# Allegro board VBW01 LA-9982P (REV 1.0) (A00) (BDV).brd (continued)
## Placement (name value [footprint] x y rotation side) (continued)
PC817  -  [C_0402NEW]  201.58 51.05 90 bottom
PC818  -  [C_0402NEW]  206.04 53.73 180 bottom
PC819  -  [C_0402NEW]  199.11 59.26 180 bottom
PC820  -  [C_0402NEW]  199.11 58.37 180 bottom
PC821  -  [C_0402NEW]  201.59 54.62 180 top
PC831  -  [C_0402NEW]  213.38 74.05 0 top
PC832  -  [C_0402NEW]  213.38 73.16 0 top
PC835  -  [C_0603NEW]  194.53 89.16 90 top
PC836  -  [C_D1]  204.04 84.58 0 top
PC837  -  [C_D1]  200.82 86.26 270 bottom
PC838  -  [C_D1]  195.99 84.68 270 bottom
PC839  -  [C_D1]  191.23 84.68 270 bottom
PC840  -  [C_0402NEW]  181.44 122.2 0 top
PC841  -  [C_0402NEW]  181.5 117.69 0 top
PC842  -  [C_0402NEW]  182.08 118.93 90 top
PC843  -  [C_0402NEW]  179.54 117.69 0 top
PC844  -  [C_0402NEW]  177.34 117.24 180 top
PC845  -  [C_0402NEW]  177.34 118.7 180 top
PC846  -  [C_0402NEW]  176.49 120.67 0 top
PC847  -  [C_0402NEW]  179.59 115.96 0 top
PC848  -  [C_0402NEW]  181.37 115.96 0 top
PC849  -  [C_0402NEW]  173.88 102.2 270 bottom
PC850  -  [C_0402NEW]  178.21 119.85 270 top
PC851  -  [C_0402NEW]  179.09 119.45 0 top
PC852  -  [C_0402NEW]  178.73 115.71 180 top
PC853  -  [C_0402NEW]  175.43 120.67 180 top
PC854  -  [C_0402NEW]  174.46 117.24 0 top
PC855  -  [C_0402NEW]  175.43 122.13 180 top
PC856  -  [C_0402NEW]  179.28 122.2 0 top
PC857  -  [C_0402NEW]  179.34 123.66 0 top
PC858  -  [C_0402NEW]  181.44 123.66 0 top
PC859  -  [C_0402NEW]  179.28 120.74 0 top
PC860  -  [C_0402NEW]  181.44 120.74 0 top
PC861  -  [C_0402NEW]  176.95 115.71 180 top
PC862  -  [C_0402NEW]  178.2 112.47 0 top
PC863  -  [C_0402NEW]  175.17 115.71 180 top
PC864  -  [C_0402NEW]  176.36 122.13 0 top
PC865  -  [C_0402NEW]  176.49 123.63 0 top
PC866  -  [C_0402NEW]  174.46 118.7 0 top
PC867  -  [C_0603NEW]  192.81 89.16 90 top
PC868  -  [C_0603NEW]  196.31 89.16 90 top
PC869  -  [C_0402NEW]  207.62 56.21 180 top
PC870  -  [C_0603NEW]  198.02 89.16 90 top
PC871  -  [C_0402NEW]  173.58 117.55 90 top
PC872  -  [C_0402NEW]  172.18 117.02 90 top
PC873  -  [C_0402NEW]  172.18 119.73 270 top
PC901  -  [C_0805NEW]  97.44 122.73 90 top
PC902  -  [C_0805NEW]  100.3 122.67 90 top
PC903  -  [C_0805NEW]  102.77 122.67 90 top
PC904  -  [C_0805NEW]  105.31 122.67 90 top
PC905  -  [C_0805NEW]  107.79 122.67 90 top
PC906  -  [C_0805NEW]  110.33 122.67 90 top
PC907  -  [C_0805NEW]  112.8 122.67 90 top
PC908  -  [C_0805NEW]  96.93 117.9 90 top
PC909  -  [C_0805NEW]  100.65 137.55 0 top
PC910  -  [C_0805NEW]  96.87 114.79 90 top
PC911  -  [C_0805NEW]  97.35 135.33 0 top
PC912  -  [C_0805NEW]  110.81 135.33 0 top
PC913  -  [C_0805NEW]  110.75 137.49 0 top
PC914  -  [C_0805NEW]  107.45 135.33 0 top
PC915  -  [C_0805NEW]  107.38 137.49 0 top
PC916  -  [C_0805NEW]  104.08 135.33 0 top
PC917  -  [C_0805NEW]  100.71 135.33 0 top
PC918  -  [C_0805NEW]  110.81 133.93 0 bottom
PC919  -  [C_0805NEW]  107.45 133.93 0 bottom
PC920  -  [C_0805NEW]  104.08 133.93 0 bottom
PC921  -  [C_0805NEW]  100.71 133.93 0 bottom
PC922  -  [C_0805NEW]  103.95 137.55 0 top
PC923  -  [C_0805NEW]  97.35 133.93 0 bottom
PC1100  -  [C_0402NEW]  178.64 173.37 0 top
PC1101  -  [C_0402NEW]  178.64 174.25 0 top
PC1102  -  [C_0805NEW]  178.82 175.59 0 top
PC1103  -  [C_0603NEW]  183.16 170.25 90 top
PC1104  -  [C_0402NEW]  188.19 172.03 180 bottom
PC1105  -  [C_0603NEW]  183.67 173.05 90 top
PC1106  -  [C_0402NEW]  181.45 170.11 90 top
PC1108  -  [C_MP6VU330MC6]  182.65 167.14 0 bottom
PC1200  -  [C_0402NEW]  183.99 186.18 90 bottom
PC1201  -  [C_0805NEW]  190.85 185.34 90 bottom
PC1202  -  [C_0805NEW]  177.8 177.49 0 bottom
PC1203  -  [C_0402NEW]  175.88 182.71 180 bottom
PC1204  -  [C_0805NEW]  177.8 179.21 0 bottom
PC1205  -  [C_0603NEW]  176.37 183.78 180 bottom
PC1206  -  [C_0805NEW]  189.07 185.34 90 bottom
PC1207  -  [C_0805NEW]  189.07 177.01 270 bottom
PC1209  -  [C_0402NEW]  175.88 181.82 180 bottom
PC1210  -  [C_0603NEW]  175.81 186.52 270 bottom
PC1211  -  [C_0805NEW]  190.78 177.01 270 bottom
PC1212  -  [C_0603NEW]  181.13 176.16 90 bottom
PC1213  -  [C_0603NEW]  178.22 185.12 90 bottom
PC1214  -  [C_0402NEW]  173.46 184.16 180 bottom
PC1300  -  [C_0805NEW]  199.1 73.38 270 top
PC1301  -  [C_0805NEW]  195 60.72 180 bottom
PC1302  -  [C_0402NEW]  194.67 62.62 180 top
PC1303  -  [C_0805NEW]  193.64 73.38 270 top
PC1304  -  [C_0402NEW]  197.15 65.03 180 top
PC1305  -  [C_0805NEW]  197.32 73.38 270 top
PC1306  -  [C_0402NEW]  197.77 63.52 270 top
PC1307  -  [C_0402NEW]  196.94 65.11 270 bottom
PC1308  -  [C_0805NEW]  195.55 73.38 270 top
PD1  -  [IP4223CZ6_SO6]  142.24 185.05 270 bottom
PD101  -  [L03ESDL5V0CG3-2_SOT-523-3]  122.63 13.98 90 top
PD701  -  [RB751V-40_SOD323-2]  162.53 171.02 0 top
PH1  -  [R_0402NEW]  106.19 113.74 0 top
PH501  -  [R_0402NEW]  95.58 143.46 0 bottom
PH502  -  [R_0402NEW]  111.93 144.16 180 bottom
PH800  -  [R_0402NEW]  203.86 79.08 270 bottom
PJP100  -  [JUMP_43X118]  134.78 13.39 270 bottom
PJP101  -  [JUMP_43X118]  122.58 13.51 270 bottom
PJP102  -  [JUMP_43X118]  140.05 13.39 270 bottom
PJP103  -  [JUMP_43X118]  117.31 13.51 270 bottom
PJP200  -  [JUMP_43X118]  149.32 27.85 90 top
PJP201  -  [JUMP_43X118]  144.81 27.59 90 bottom
PJP203  -  [JUMP_43X39]  155.03 29.36 270 bottom
PJP300  -  [JUMP_43X118]  143.67 140.45 270 top
PJP400  -  [JUMP_43X79]  108.3 20.35 90 bottom
PJP401  -  [JUMP_43X79]  112.11 31.27 90 bottom
PJP600  -  [JUMP_43X79]  213.98 90.82 0 bottom
PJP601  -  [JUMP_43X79]  215.29 96.76 270 top
PJP1100  -  [JUMP_43X118]  182.78 162.32 270 bottom
PJP1101  -  [JUMP_43X118]  188.12 162.32 270 bottom
PJP1200  -  [JUMP_43X118]  192.27 181.37 0 bottom
PJP1300  -  [JUMP_43X79]  195.74 76.19 270 top
PJP1301  -  [JUMP_43X79]  194.66 58.76 270 bottom
PJPDC  -  [ACES_50299-00501-003_5P]  136.9 178.4 270 bottom
PL1  -  [CHT_C8BBPH853025_2P]  140.43 174 270 bottom
PL2  -  [CHT_C8BBPH853025_2P]  132.93 182.51 180 bottom
PL3  -  [CHENG_SMB3025500YA_2P]  155.86 180.26 90 bottom
PL4  -  [CHT_C8BBPH853025_2P]  132.87 166.13 180 bottom
PL100  -  [VISHAY_IHLP-2525CZ-01_2P]  135.35 25.41 0 bottom
PL101  -  [VISHAY_IHLP-2525CZ-01_2P]  120.17 25.57 180 bottom
PL102  -  [CYNTE_PCMB053T-1R0MS_2P]  127.73 31.78 270 bottom
PL200  -  [TAI-T_VMPI0703AR-1R0M-Z01_2P]  145.4 15.12 0 bottom
PL201  -  [L_1812-1806]  165.32 20.69 270 bottom
PL301  -  [CYNTE_PCMB063T-1R0MS_2P]  144.08 150.59 270 bottom
PL302  -  [L_1812-1806]  134.42 158.32 0 bottom
PL400  -  [CYNTE_PH041H-1R0MS_2P]  107.58 28.97 90 bottom
PL501  -  [L_1812-1806]  135.09 146.53 90 bottom
PL502  -  [TOKO_FDUE1040J-H-R36M-P3_4P]  109.67 140.16 180 bottom
PL600  -  [CYNTE_PH041H-1R0MS_2P]  219.55 94.6 90 bottom
PL701  -  [TOKO_FDVE1040-H-2R2M-P3_2P]  155.38 172.6 180 bottom
PL702  -  [CYNTE_PCMB053T-1R0MS_2P]  146.89 163.46 0 bottom
PL800  -  [L_1812-1806]  217.55 77.93 180 top
PL802  -  [MAG_MMD-12CE-R36M-M1L_2P]  211.17 74.49 90 bottom
PL1100  -  [TAI-T_HCB2012KF-121T50_2P]  175.16 177.38 90 top
PL1101  -  [PANAS_ETQP3W2R2WFN_2P]  177.13 170.14 90 bottom
PL1200  -  [CYNTE_PCMB063T-1R0MS_2P]  183.29 181.24 0 bottom
PL1201  -  [L_1812-1806]  171.44 178.76 0 bottom
PL1300  -  [VISHAY_IHLP-2525CZ-01_2P]  195.55 71.38 90 bottom
PQ1  -  [2N7002DW-T-R7_SOT363-6]  128.22 173.52 0 top
PQ2  -  [2N7002DW-T-R7_SOT363-6]  128.9 168.81 270 top
PQ3  -  [2N7002DW-T-R7_SOT363-6]  128.96 163.6 270 top
PQ4  -  [SSM3K7002FU_SC70-3]  128.17 179.34 0 top
PQ5  -  [RHU002N06_SOT323-3]  133.89 187.37 0 bottom
PQ6  -  [FDV301N_NL_SOT23-3]  128.97 186.57 90 bottom
PQ101  -  [SIS412DN-T1-GE3_POWERPAK8-5]  133.1 26.55 90 top
PQ102  -  [SIS412DN-T1-GE3_POWERPAK8-5]  130.23 24.72 270 top
PQ103  -  [SIS412DN-T1-GE3_POWERPAK8-5]  121.78 28.7 270 top
PQ104  -  [SIS412DN-T1-GE3_POWERPAK8-5]  124.65 22.93 90 top
PQ200  -  [SIS412DN-T1-GE3_POWERPAK8-5]  154.68 16.29 90 bottom
PQ201  -  [SIS412DN-T1-GE3_POWERPAK8-5]  157.04 14.46 270 bottom
PQ701  -  [CSD87312Q3E_SON8-4]  140.24 167.98 0 bottom
PQ702  -  [AO4407AL_SO8]  147.12 178.89 90 bottom
PQ703  -  [MDU1516URH_POWERDFN56-8-5]  156.11 169.3 180 top
PQ704  -  [MDU1516URH_POWERDFN56-8-5]  149.77 169.32 180 top
PQ705  -  [MDU1511RH_POWERDFN56-8-5]  159.54 171.17 90 top
PQ706  -  [SSM3K7002FU_SC70-3]  135.79 168.22 180 top
PQ708  -  [SSM3K7002FU_SC70-3]  171.48 173.11 0 top
PQ800  -  [SIR472DP-T1-GE3_POWERPAK8-5]  205.77 69.39 270 top
PQ801  -  [SIR818DP-T1_POWERPAK-SO8-5]  214.09 65.47 270 bottom
PQ802  -  [SIR818DP-T1_POWERPAK-SO8-5]  214.09 71.26 270 bottom
PQ803  -  [SIR472DP-T1-GE3_POWERPAK8-5]  205.77 75.39 270 top
PQ1100  -  [SIS412DN-T1-GE3_POWERPAK8-5]  175.38 172.25 0 top
PQ1101  -  [SIS412DN-T1-GE3_POWERPAK8-5]  180.28 174.79 270 bottom
PQ1201  -  [2N7002W-T-R7_SOT323-3]  173.45 186.99 0 bottom
PR1  -  [R_0402NEW]  128.63 171.02 0 top
PR3  -  [R_0402NEW]  132.35 185.62 0 top
PR4  -  [R_0402NEW]  130.57 185.62 0 top
PR5  -  [R_1206NEW]  131.27 175.59 270 top
PR6  -  [R_0402NEW]  132.5 182.7 180 top
PR7  -  [R_0402NEW]  128.86 177.49 0 top
PR8  -  [R_0402NEW]  134.22 187.46 180 top
PR9  -  [R_0402NEW]  134.28 182.7 180 top
PR10  -  [R_0402NEW]  129.77 176.6 180 top
PR15  -  [R_0402NEW]  138.54 184.92 180 bottom
PR16  -  [R_0402NEW]  136.76 184.92 180 bottom
PR18  -  [R_0402NEW]  141.88 183.65 0 top
PR20  -  [R_0402NEW]  141.88 184.54 0 top
PR23  -  [R_0402NEW]  129.94 179.91 0 top
PR24  -  [R_0402NEW]  181.96 45.02 90 bottom
PR26  -  [R_0402NEW]  130.85 181.68 180 top
PR27  -  [R_0402NEW]  129.11 178.89 0 top
PR28  -  [R_0402NEW]  128.38 166.38 180 top
PR29  -  [R_0402NEW]  127.65 170 0 top
PR30  -  [R_0402NEW]  127.54 161.8 90 top
PR31  -  [R_0402NEW]  131.98 167.7 90 top
PR32  -  [R_0402NEW]  132.11 162.71 270 top
PR33  -  [R_0402NEW]  130.51 166.32 0 top
PR100  -  [R0402_0OHM-NEW]  120.98 13.13 180 top
PR101  -  [R0402_0OHM-NEW]  120.98 14.91 180 top
PR102  -  [R_0402NEW]  120.98 14.02 180 top
PR103  -  [R_0402NEW]  132.44 16.68 180 top
PR104  -  [R_0402NEW]  126.71 12.98 270 top
PR105  -  [R_0402NEW]  125.82 12.98 270 top
PR106  -  [R_0402NEW]  125.72 12.99 270 bottom
PR107  -  [R_0402NEW]  130.71 12.06 90 top
PR108  -  [R_0402NEW]  131.6 12.98 270 top
PR109  -  [R_0402NEW]  128.93 12.06 90 top
PR111  -  [R_0402NEW]  124.12 17.28 180 top
PR112  -  [R_1206NEW]  119.98 25.06 270 top
PR113  -  [R_1206NEW]  134.97 24.87 270 top
PR114  -  [R_0402NEW]  124.12 15.5 180 top
PR200  -  [R_0603NEW]  154.85 22.95 90 bottom
PR201  -  [R_0402NEW]  162.92 25.22 180 bottom
PR202  -  [R_0402NEW]  162.92 27 180 bottom
PR203  -  [R_1206NEW]  161.32 10.74 0 bottom
PR204  -  [R_0402NEW]  161.47 29.11 180 bottom
PR205  -  [R_0402NEW]  158.59 20.28 90 bottom
PR206  -  [R_0603NEW]  162.09 21.42 270 bottom
PR207  -  [R_0402NEW]  161.47 28.22 180 bottom
PR208  -  [R_0402NEW]  162.92 23.44 180 bottom
PR300  -  [R_0402NEW]  148.17 148.34 0 bottom
PR301  -  [R_0402NEW]  148.17 149.23 0 bottom
PR302  -  [R_1206NEW]  139.54 146.56 90 bottom
PR303  -  [R_0603NEW]  147.04 156.85 0 bottom
PR304  -  [R_0402NEW]  149.08 152.78 180 bottom
PR305  -  [R_0402NEW]  148.62 153.72 90 bottom
PR306  -  [R_0402NEW]  148.17 151.89 0 bottom
PR307  -  [R_0402NEW]  149.39 155.5 90 bottom
PR308  -  [R_0402NEW]  149.08 151.01 180 bottom
PR401  -  [R_0402NEW]  113.68 26.85 270 bottom
PR402  -  [R_0402NEW]  111.9 23.78 90 bottom
PR403  -  [R_0402NEW]  112.79 24.69 270 bottom
PR404  -  [R_0402NEW]  112.79 26.85 270 bottom
PR405  -  [R_0603NEW]  108.34 26.97 180 bottom
PR501  -  [R_0402NEW]  88.61 141.22 90 bottom
PR502  -  [R_0402NEW]  85.94 141.22 90 bottom
PR503  -  [R_0402NEW]  88.48 138.94 90 top
PR504  -  [R_0402NEW]  86.83 141.22 90 bottom
PR505  -  [R_0402NEW]  86.71 138.94 90 top
PR506  -  [R_0402NEW]  85.82 138.94 90 top
PR507  -  [R_0402NEW]  87.72 141.22 90 bottom
PR508  -  [R_0402NEW]  91.66 142.19 270 bottom
PR509  -  [R_0402NEW]  87.6 138.94 90 top
PR510  -  [R_0402NEW]  87.01 137.23 0 top
PR512  -  [R_0402NEW]  89.37 138.94 90 top
PR513  -  [R_0402NEW]  91.15 138.94 90 top
PR514  -  [R_0402NEW]  90.77 141.29 90 bottom
PR515  -  [R_0402NEW]  92.98 141.74 0 bottom
PR516  -  [R_0603NEW]  83.98 135.77 0 bottom
PR517  -  [R_0402NEW]  92.98 140.85 0 bottom
PR518  -  [R_0402NEW]  92.93 143.06 90 bottom
PR519  -  [R_0603NEW]  88.87 131.89 90 bottom
PR522  -  [R_0402NEW]  85.46 139.01 180 bottom
PR524  -  [R_0402NEW]  84.55 137.23 0 bottom
PR526  -  [R_0402NEW]  87.79 132.59 90 bottom
PR528  -  [R_0402NEW]  86.9 132.59 90 bottom
PR529  -  [R_0402NEW]  92.66 132.6 0 bottom
PR530  -  [R_0402NEW]  84.53 134.69 0 bottom
PR531  -  [R_0402NEW]  90.9 132.66 90 bottom
PR532  -  [R_0402NEW]  93.58 133.49 180 bottom
PR533  -  [R_0402NEW]  85.45 134.69 180 top
PR534  -  [R_1206NEW]  108.42 143.2 0 top
PR535  -  [R0402_0OHM-NEW]  85.46 138.12 180 bottom
PR536  -  [R_0603NEW]  116.36 139.9 0 bottom
PR540  -  [R_0402NEW]  84.53 135.58 0 top
PR601  -  [R_0402NEW]  218.29 93.36 180 top
PR602  -  [R_0402NEW]  221.26 89.79 90 bottom
PR603  -  [R_0402NEW]  222.16 88.91 180 bottom
PR604  -  [R_0402NEW]  219.17 93.37 270 top
PR605  -  [R_0603NEW]  216.06 95.13 270 bottom
PR701  -  [R_0402NEW]  142.9 163.89 90 bottom
PR702  -  [R_1206_4P-D]  139.7 162.19 0 bottom
PR703  -  [R_0402NEW]  143.79 164.81 270 bottom
PR704  -  [R_0402NEW]  166.78 165.95 270 bottom
PR705  -  [R_1206NEW]  164.49 163.08 90 top
PR706  -  [R_0402NEW]  147.36 183.91 180 bottom
PR707  -  [R_0402NEW]  169.07 164.97 90 top
PR708  -  [R_0402NEW]  167.67 173.04 90 top
PR709  -  [R_0603NEW]  163.92 169.56 180 top
PR710  -  [R_0402NEW]  168.56 173.04 90 top
PR711  -  [R_0402NEW]  172.25 167.21 180 top
PR712  -  [R_0402NEW]  170.02 165.89 270 top
PR713  -  [R_0402NEW]  171.34 171.65 0 top
PR714  -  [R0402_0OHM-NEW]  172.25 170.76 180 top
PR715  -  [R0402_0OHM-NEW]  172.25 169.87 180 top
PR716  -  [R_1206_4P-D]  143.73 176.64 90 bottom
PR717  -  [R_0402NEW]  167.67 165.95 270 bottom
PR720  -  [R_1206NEW]  138.2 169.94 180 top
PR721  -  [R_0402NEW]  143.81 165.68 180 bottom
PR722  -  [R_1206NEW]  156.37 177.01 0 top
PR723  -  [R_0402NEW]  171.34 166.32 0 top
PR724  -  [R_0402NEW]  171.07 176.22 0 top
PR802  -  [R_0603NEW]  201.39 60.08 90 bottom
PR803  -  [R_0402NEW]  209.91 56.02 180 bottom
PR804  -  [R_0402NEW]  206.71 57.1 0 top
PR805  -  [R_1206NEW]  211.17 62.69 0 top
PR806  -  [R_0402NEW]  209.91 56.91 180 bottom
PR807  -  [R_0402NEW]  209.91 58.68 180 bottom
PR808  -  [R_0402NEW]  209.91 54.24 180 bottom
PR809  -  [R_0402NEW]  209.91 57.8 180 bottom
PR810  -  [R_0402NEW]  208.7 59 180 top
PR811  -  [R_0402NEW]  206.96 60.46 0 top
PR812  -  [R_0402NEW]  209.91 59.57 180 bottom
PR813  -  [R_0402NEW]  203.37 51.95 180 bottom
PR814  -  [R_0603NEW]  205.9 61.73 90 bottom
PR815  -  [R_0402NEW]  206.72 54.35 90 top
PR816  -  [R_0402NEW]  199.11 56.59 180 bottom
PR817  -  [R_0402NEW]  206.04 52.84 180 bottom
PR818  -  [R_0402NEW]  203.37 51.06 180 bottom
PR819  -  [R_0402NEW]  207.79 58.11 0 top
PR820  -  [R_0402NEW]  205.32 53.49 270 top
PR821  -  [R_0402NEW]  204.24 53.74 270 bottom
PR822  -  [R_0603NEW]  201.51 58.68 180 bottom
PR823  -  [R_0603NEW]  201.51 58.68 180 top
PR824  -  [R_0402NEW]  201.58 60.67 270 top
PR825  -  [R_0402NEW]  201.59 55.51 180 bottom
PR826  -  [R_0402NEW]  213.91 59.51 180 bottom
PR827  -  [R_0402NEW]  199.11 57.48 180 bottom
PR828  -  [R_0402NEW]  209.64 58.1 90 top
PR829  -  [R_0402NEW]  199.1 61.05 270 bottom
PR830  -  [R_0402NEW]  198.21 61.05 270 bottom
PR833  -  [R_0402NEW]  200.69 56.41 270 top
PR834  -  [R_0402NEW]  211.22 59.57 0 bottom
PR835  -  [R_0402NEW]  213.91 57.99 180 bottom
PR836  -  [R_0402NEW]  211.22 57.99 0 bottom
PR837  -  [R_0402NEW]  213.91 57.1 180 bottom
PR838  -  [R_0402NEW]  211.22 57.1 0 bottom
PR839  -  [R_0402NEW]  213.91 55.57 180 bottom
PR840  -  [R_0402NEW]  211.22 55.57 0 bottom
PR842  -  [R_0402NEW]  208.99 55.13 0 bottom
PR845  -  [R_0402NEW]  200.63 54.63 270 bottom
PR846  -  [R_0402NEW]  203.37 53.73 180 bottom
PR1101  -  [R_0603NEW]  185.07 169.17 180 top
PR1102  -  [R_0402NEW]  187.28 171.14 0 bottom
PR1103  -  [R_0402NEW]  189.89 173.19 270 top
PR1104  -  [R_1206NEW]  177.57 170.44 0 top
PR1105  -  [R_0402NEW]  188.19 173.81 180 bottom
PR1107  -  [R_0402NEW]  189.89 172.87 270 bottom
PR1108  -  [R_0402NEW]  188.19 172.92 180 bottom
PR1110  -  [R_0402NEW]  189.21 169.68 180 top
PR1200  -  [R_0603NEW]  177.01 185.12 90 bottom
PR1201  -  [R_0402NEW]  184.88 186.18 90 bottom
PR1202  -  [R_0402NEW]  182.21 186.18 90 bottom
PR1203  -  [R_0402NEW]  181.32 187.09 270 bottom
PR1204  -  [R_0402NEW]  178.36 187.47 180 bottom
PR1206  -  [R_0402NEW]  185.77 186.18 90 bottom
PR1207  -  [R_1206NEW]  185.13 176.67 180 bottom
PR1208  -  [R_0402NEW]  180.45 188.22 180 bottom
PR1209  -  [R_0402NEW]  179.54 185.54 90 bottom
PR1210  -  [R_0402NEW]  179.53 187.34 0 bottom
PR1211  -  [R_0402NEW]  176.06 187.46 180 bottom
PR1212  -  [R_0402NEW]  172.55 183.27 0 bottom
PR1213  -  [R_0402NEW]  170.72 184.17 270 bottom
PR1214  -  [R_0402NEW]  171.61 183.26 90 bottom
PR1300  -  [R_0402NEW]  197.84 65.99 180 bottom
PR1301  -  [R_0402NEW]  195.99 62.61 90 top
PR1302  -  [R_0402NEW]  196.88 63.52 270 top
PR1303  -  [R_1206NEW]  196.62 68.91 270 top
PR1304  -  [R_0402NEW]  197.89 65.11 270 bottom
PU100  -  [TPS51225CRUKR_QFN20_3X3]  127.03 14.52 0 top
PU200  -  [RT8207MZQW_WQFN20_3X3]  157.71 26.38 0 bottom
PU300  -  [SY8206DQNC_QFN10_3X3]  145.59 153.63 90 bottom
PU400  -  [SY8003DFC_DFN8_2X2]  110.87 24.22 180 bottom
PU501  -  [TPS51622RSM_QFN32_4X4]  87.18 136.02 90 bottom
PU502  -  [CSD97374CQ4M_SON8_3P5X4P5]  111.9 139.63 90 bottom
PU600  -  [SY8003DFC_DFN8_2X2]  220.04 90.16 180 bottom
PU701  -  [BQ24738RGRR_QFN20_3P5X3P5]  166.99 167.7 0 top
PU800  -  [ISL62881HRZ-T_QFN28_4X4]  206.59 55.46 180 bottom
PU1100  -  [TPS51212DSCR_SON10_3X3]  188.26 171.29 90 top
PU1200  -  [SY8206DQNC_QFN10_3X3]  180.29 183.54 180 bottom
PU1300  -  [SY8036DBC_DFN10_3X3]  193.66 65.57 0 bottom
Q8  -  [2N7002K_SOT23-3]  87.21 23.02 180 top
Q2307  -  [2N7002K_SOT23-3]  182.97 60.17 180 top
Q2308  -  [2N7002K_SOT23-3]  147.9 121.17 270 top
QA5  -  [DMN66D0LDW-7_SOT363-6]  25.85 27.08 270 bottom
QA6  -  [DMN66D0LDW-7_SOT363-6]  15.93 20.7 90 bottom
QC1  -  [DMN66D0LDW-7_SOT363-6]  144.74 110.07 0 bottom
QC3  -  [2N7002K_SOT23-3]  134.62 130.95 180 bottom
QD2  -  [BSS138-G_SOT23-3]  48.7 64.91 90 top
QD18  -  [2N7002K_SOT23-3]  57.9 16.58 90 top
QH1  -  [DMN66D0LDW-7_SOT363-6]  148.21 115.18 270 bottom
QM30  -  [2N7002K_SOT23-3]  102.42 147.33 90 top
QS2  -  [SI3456BDV-T1-E3_TSOP6]  220.85 121.09 0 bottom
QS3  -  [2N7002KW_SOT323-3]  221.49 125.83 0 bottom
QV14  -  [DMN66D0LDW-7_SOT363-6]  188.48 101.22 0 bottom
QV15  -  [DMN66D0LDW-7_SOT363-6]  178.54 93.83 180 top
QV22  -  [AP2301GN-HF_SOT23-3]  184.15 93.73 90 bottom
QV24  -  [2N7002K_SOT23-3]  179 90.24 270 bottom
QV25  -  [2N7002K_SOT23-3]  174.36 90.05 270 bottom
QV28  -  [2N7002K_SOT23-3]  183.16 90.53 0 top
QX1  -  [2N7002KW_SOT323-3]  216.84 176.48 90 top
QX2  -  [SI3457CDV-T1-GE3_TSOP6]  223.09 176.67 180 top
QX3  -  [2N7002K_SOT23-3]  19.12 106.82 90 bottom
QX4  -  [DMN66D0LDW-7_SOT363-6]  15.19 106.76 0 top
QX5  -  [MMBT3904_NL_SOT23-3]  16.6 113.14 180 bottom
QX6  -  [DMN66D0LDW-7_SOT363-6]  196.11 163.13 90 top
R1  -  [R_0402NEW]  93.64 134.06 180 top
R2  -  [R_0402NEW]  91.86 134.06 180 top
R10  -  [R_0402NEW]  85.69 24.72 270 top
R16  -  [R_0402NEW]  87.84 19.19 0 top
R159  -  [R_0402NEW]  147.53 102.56 0 top
R245  -  [R_0603NEW]  93.12 129.93 90 bottom
R248  -  [R_0402NEW]  80.85 117.8 0 bottom
R250  -  [R_0402NEW]  91.98 122.11 90 top
R251  -  [R_0402NEW]  90.52 129.69 270 bottom
R252  -  [R_0402NEW]  80.85 118.69 0 bottom
R253  -  [R_0402NEW]  81.77 120.6 180 bottom
R254  -  [R_0402NEW]  84.12 118.69 180 bottom
R255  -  [R_0402NEW]  83.2 120.98 0 bottom
R256  -  [R_0402NEW]  79.92 119.58 0 bottom
R257  -  [R0402_0OHM-NEW]  79.92 120.53 180 bottom
R264  -  [R_0603NEW]  150.97 104.66 180 top
R265  -  [R_0402NEW]  118.33 98.19 270 top
R267  -  [R_0805NEW]  123.83 140.85 0 bottom
R286  -  [R_0402NEW]  92.04 129.69 270 bottom
R416  -  [R_0402NEW]  143.04 19.76 180 bottom
R2313  -  [R_0402NEW]  96.8 25.59 90 top
R2314  -  [R_0603NEW]  184.62 62.49 270 top
R2315  -  [R_0603NEW]  146.9 124.09 270 top
R2318  -  [R_0402NEW]  93.44 25.65 90 top
R2329  -  [R_0402NEW]  140.87 109.06 0 bottom
R2330  -  [R_0402NEW]  135.28 103.66 270 bottom
R2331  -  [R_0402NEW]  147.04 109 270 bottom
R2332  -  [R_0402NEW]  147.93 110.06 180 bottom
R2333  -  [R_0402NEW]  142.55 115.86 180 bottom
R2334  -  [R_0402NEW]  142.55 116.75 180 bottom
R2335  -  [R_0402NEW]  142.55 117.63 180 bottom
R2336  -  [R_0402NEW]  125.72 96.24 90 top
R2337  -  [R_0402NEW]  134.01 99.65 270 bottom
R2338  -  [R_0402NEW]  133.12 99.65 270 bottom
R2341  -  [R_0402NEW]  75.29 114.06 180 top
R2346  -  [R_0402NEW]  79.91 122.5 90 bottom
R2347  -  [R_0402NEW]  43.97 63.82 90 top
R2348  -  [R_0402NEW]  43.08 62.98 270 top
R2349  -  [R_0402NEW]  43.97 62.98 270 top
R2350  -  [R_0402NEW]  42.19 62.98 270 top
R2351  -  [R_0402NEW]  44.86 63.82 90 top
R2352  -  [R_0402NEW]  41.3 62.98 270 top
R2354  -  [R_0402NEW]  187.42 32.7 90 top
R2355  -  [R_0402NEW]  32.15 20.52 0 top
R2356  -  [R_0402NEW]  127.24 97.04 90 bottom
R2357  -  [R_0402NEW]  130.9 97.48 180 bottom
R2358  -  [R_0402NEW]  129.05 97.04 90 bottom
R2359  -  [R_0402NEW]  128.16 97.04 90 bottom
RA1  -  [R_0402NEW]  30.57 28.28 270 top
RA2  -  [R_0402NEW]  21.84 26.56 0 bottom
RA3  -  [R_0402NEW]  28.73 23.56 90 bottom
RA4  -  [R0402_0OHM-NEW]  30.57 25.59 90 top
RA5  -  [R_0402NEW]  17.62 25.49 270 bottom
RA6  -  [R_0402NEW]  15.78 25.49 270 bottom
RA7  -  [R_0402NEW]  16.69 25.49 270 bottom
RA8  -  [R_0402NEW]  25.66 14.74 90 top
RA9  -  [R_0402NEW]  24.78 14.74 90 top
RA19  -  [R_0402NEW]  36.62 23.63 180 top
RA29  -  [R0603_0OHM-NEW]  23.9 21.6 0 bottom
RA30  -  [R0603_0OHM-NEW]  26.57 23.76 270 bottom
RA31  -  [R0603_0OHM-NEW]  23.27 26.81 90 top
RA32  -  [R0603_0OHM-NEW]  26.84 12.05 0 top
RA51  -  [R_0402NEW]  29.68 25.59 90 top
RA53  -  [R_0402NEW]  15.84 23.37 90 top
RA55  -  [R_0402NEW]  24.04 11.61 0 bottom
RA56  -  [R_0402NEW]  24.04 12.49 0 bottom
RA79  -  [R_0402NEW]  33.93 24.52 0 top
RA80  -  [R_0402NEW]  21.82 20.14 180 bottom
RA81  -  [R_0402NEW]  34.84 25.41 180 top
RA82  -  [R_0402NEW]  21.82 21.03 180 bottom
RA83  -  [R_0402NEW]  20.04 20.14 180 top
RA84  -  [R_0402NEW]  20.04 21.92 180 top
RA130  -  [R_0402NEW]  33.06 21.47 180 top
RA131  -  [R_0402NEW]  32.15 19.25 0 top
RA153  -  [R_0402NEW]  28.48 26.82 270 top
RA165  -  [R_0402NEW]  21.82 20.14 180 top
RA166  -  [R_0402NEW]  21.82 21.03 180 top
RA1109  -  [R_0402NEW]  16.73 23.37 90 top
RC1  -  [R_0402NEW]  132.3 97.31 270 bottom
RC2  -  [R_0402NEW]  133.19 96.54 270 bottom
RC3  -  [R_0402NEW]  125.45 97.04 90 bottom
RC4  -  [R_0402NEW]  146 98.25 0 bottom
RC5  -  [R_0402NEW]  131.28 94.74 90 top
RC6  -  [R_0402NEW]  132.17 94.74 90 top
RC7  -  [R_0402NEW]  134.9 98.74 90 bottom
RC8  -  [R_0402NEW]  126.34 97.04 90 bottom
RC9  -  [R_0402NEW]  135.08 115.71 0 top
RC10  -  [R_0402NEW]  204.05 9.8 270 bottom
RC11  -  [R_0402NEW]  131.61 118.31 180 top
RC12  -  [R_0402NEW]  116.23 134.46 0 top
RC13  -  [R_0402NEW]  115.54 129.22 90 bottom
RC14  -  [R_0402NEW]  97.96 91.07 90 bottom
RC15  -  [R_0402NEW]  94.59 91.07 90 bottom
RC16  -  [R_0402NEW]  96.99 90.44 180 bottom
RC17  -  [R_0402NEW]  97.07 93.74 90 bottom
RC18  -  [R_0402NEW]  94.4 93.74 90 bottom
RC19  -  [R_0402NEW]  96.18 93.74 90 bottom
RC20  -  [R_0402NEW]  97.05 92.86 0 bottom
RC21  -  [R_0402NEW]  94.41 92.86 180 bottom
RC22  -  [R_0402NEW]  96.19 92.86 180 bottom
RC23  -  [R_0402NEW]  97.96 94.65 270 bottom
RC24  -  [R_0402NEW]  93.51 94.65 270 bottom
RC25  -  [R_0402NEW]  95.29 94.65 270 bottom
RC26  -  [R_0402NEW]  61.63 106.21 270 top
RC27  -  [R_0402NEW]  136.82 96.39 180 top
RC28  -  [R_0402NEW]  148.42 108.98 0 bottom
RC29  -  [R_0402NEW]  148.11 111.72 0 bottom
RC31  -  [R_0402NEW]  147.87 108.79 180 top
RC32  -  [R_0402NEW]  144.38 114.44 180 bottom
RC33  -  [R_0402NEW]  126.98 98.18 180 top
RC34  -  [R_0402NEW]  130.9 110.26 270 top
RC35  -  [R_0402NEW]  134.08 97.31 270 top
RC36  -  [R_0402NEW]  129.77 114.35 180 top
RC37  -  [R_0402NEW]  133.44 109.17 180 bottom
RC41  -  [R_0402NEW]  128 97.05 180 top
RC42  -  [R_0402NEW]  134.97 96.39 90 top
RC43  -  [R_0402NEW]  74.49 106.46 180 bottom
RC44  -  [R_0402NEW]  74.54 104.21 180 bottom
RC45  -  [R_0402NEW]  74.54 105.12 180 bottom
RC46  -  [R_0402NEW]  65.94 104.36 0 bottom
RC48  -  [R_0402NEW]  65.44 90.12 90 bottom
RC49  -  [R_0402NEW]  63.67 90.12 90 bottom
RC50  -  [R_0402NEW]  62.78 90.12 90 bottom
RC51  -  [R_0402NEW]  62.78 102.27 270 bottom
RC52  -  [R_0402NEW]  61.89 90.12 90 bottom
RC56  -  [R_0402NEW]  58.71 101.36 90 bottom
RC57  -  [R_0402NEW]  75.29 114.95 180 top
RC58  -  [R_0402NEW]  89.17 119.58 0 top
RC59  -  [R_0402NEW]  83.71 110.69 0 bottom
RC60  -  [R_0402NEW]  88.3 120.03 90 top
RC62  -  [R_0402NEW]  83.71 111.58 0 bottom
RC63  -  [R_0402NEW]  89.77 112.02 180 top
RC64  -  [R_0402NEW]  62.78 88.68 270 bottom
RC65  -  [R_0402NEW]  83.71 109.8 0 bottom
RC66  -  [R_0402NEW]  89.2 128.85 180 bottom
RC67  -  [R_0402NEW]  89.56 120.93 0 top
RC68  -  [R_0402NEW]  89.32 98.15 270 top
RC69  -  [R_0402NEW]  90.21 98.15 270 top
RC70  -  [R_0402NEW]  88.43 98.15 270 top
RC71  -  [R_0402NEW]  117.75 124.03 0 top
RC72  -  [R_0402NEW]  103.34 128.73 90 bottom
RC73  -  [R_0402NEW]  137.13 118.45 270 bottom
RC74  -  [R_0402NEW]  125.19 116.2 90 top
RC75  -  [R_0402NEW]  131.04 134.81 180 bottom
RC76  -  [R_0402NEW]  136.25 119.33 180 bottom
RC77  -  [R_0402NEW]  129.45 118.57 180 top
RC78  -  [R_0402NEW]  135.17 129.21 180 bottom
RC81  -  [R0402_0OHM-NEW]  129.25 133.92 90 bottom
RC84  -  [R_0402NEW]  131.04 133.92 180 bottom
RC87  -  [R_0402NEW]  126.27 123.7 90 top
RC88  -  [R_0402NEW]  133.49 119.2 0 bottom
RC89  -  [R_0402NEW]  133.14 129.21 90 bottom
RC90  -  [R_0402NEW]  122.51 110.41 90 top
RC91  -  [R_0402NEW]  113.74 129.3 0 bottom
RC97  -  [R_0402NEW]  130.89 108.47 0 top
RC98  -  [R_0402NEW]  128.54 119.45 0 top
RC99  -  [R_0402NEW]  134.2 115.89 90 top
RC100  -  [R_0402NEW]  136 116.6 180 top
RC101  -  [R_0402NEW]  124.28 97.15 270 bottom
RC102  -  [R_0402NEW]  143.85 119.66 0 bottom
RC103  -  [R_0402NEW]  148.19 112.6 180 bottom
RC104  -  [R_0402NEW]  141.78 109.94 180 bottom
RC105  -  [R_0402NEW]  132.26 130.12 270 bottom
RC106  -  [R_0402NEW]  136.25 121.99 180 bottom
RC107  -  [R_0402NEW]  145 111.06 0 bottom
RC108  -  [R_0402NEW]  136.64 121.12 180 bottom
RC110  -  [R_0402NEW]  145 111.92 0 bottom
RC111  -  [R_0402NEW]  136.63 120.22 180 bottom
RC112  -  [R_0402NEW]  134.6 119.33 180 top
RC113  -  [R_0402NEW]  133.68 118.44 0 top
RC116  -  [R_0402NEW]  133.49 118.31 0 bottom
RC118  -  [R_0402NEW]  136.25 125.87 180 bottom
RC119  -  [R_0402NEW]  136.25 118.44 180 bottom
RC120  -  [R_0402NEW]  146.11 112.8 180 bottom
RC121  -  [R_0402NEW]  136.5 114.25 180 bottom
RC122  -  [R_0402NEW]  134.41 125.58 180 bottom
RC123  -  [R_0402NEW]  133.49 120.09 0 bottom
RC124  -  [R_0402NEW]  148.43 107.21 0 bottom
RC125  -  [R_0402NEW]  148.43 108.1 0 bottom
RC126  -  [R_0603NEW]  123.35 130.63 90 bottom
RC127  -  [R_0402NEW]  123.21 98.19 180 top
RC128  -  [R_0402NEW]  123.21 97.31 180 top
RC129  -  [R_0402NEW]  123.21 96.43 180 top
RC130  -  [R_0402NEW]  85.56 110.68 90 bottom
RC131  -  [R_0402NEW]  124.43 130.62 90 bottom
RC132  -  [R_0402NEW]  91.72 115.66 0 top
RC133  -  [R_0402NEW]  122.27 131.47 270 bottom
RC134  -  [R_0402NEW]  123.39 97.15 270 bottom
RC135  -  [R_0402NEW]  84.62 108.91 180 bottom
RC138  -  [R_0402NEW]  82.6 113.5 180 bottom
RC139  -  [R_0402NEW]  108.36 129.69 270 bottom
RC140  -  [R_0402NEW]  109.31 129.69 270 bottom
RC141  -  [R_0402NEW]  84.12 120.03 180 bottom
RC163  -  [R_0402NEW]  89.58 124.03 180 top
RC362  -  [R_0402NEW]  60.99 102.26 270 bottom
RD1  -  [R0402_0OHM-NEW]  43.54 70.05 180 top
RD3  -  [R_0402NEW]  49.48 63.45 0 top
RD4  -  [R0402_0OHM-NEW]  83.46 63.45 0 top
RD5  -  [R0402_0OHM-NEW]  83.46 62.56 0 top
RD6  -  [R_0402NEW]  102.44 68.78 0 top
RD7  -  [R_0402NEW]  102.44 67.89 0 top
RD8  -  [R0402_0OHM-NEW]  121.33 70.75 180 top
RD10  -  [R0402_0OHM-NEW]  162.07 62.56 0 top
RD12  -  [R_0402NEW]  182.79 65.73 180 top
RD13  -  [R_0402NEW]  182.78 70.48 90 top
RD14  -  [R_0402NEW]  34.65 10.81 180 top
RD15  -  [R_0402NEW]  43.98 10.74 180 top
RD16  -  [R_0402NEW]  49.9 13.86 270 top
RD17  -  [R_0402NEW]  49.01 13.86 270 top
RD18  -  [R_0402NEW]  57.93 12.9 0 top
RD45  -  [R_0402NEW]  54 15.9 270 top
RD46  -  [R_0402NEW]  58.84 13.79 180 top
RE1  -  [R_0402NEW]  93.77 121.8 180 top
RE2  -  [R_0402NEW]  128.11 94.8 90 top
RE3  -  [R_0402NEW]  197.2 53.78 90 top
RE5  -  [R_0402NEW]  195.42 54.7 270 top
RE7  -  [R_0402NEW]  192.05 54.63 270 top
RE8  -  [R_0402NEW]  199.47 38.94 0 top
RE9  -  [R_0402NEW]  187.04 54.19 270 top
RE10  -  [R_0402NEW]  186.15 54.19 270 top
RE11  -  [R_0402NEW]  181.35 34.16 270 top
RE12  -  [R_0402NEW]  179.59 40.41 180 top
RE18  -  [R_0402NEW]  195.93 33.81 270 top
RE36  -  [R_0402NEW]  178.58 45.86 0 top
RE37  -  [R_0402NEW]  127.84 98.18 0 top
RE43  -  [R_0402NEW]  179.43 41.68 180 top
RE44  -  [R0402_0OHM-NEW]  180.5 54.38 270 top
RE47  -  [R_0402NEW]  178.27 50.35 90 top
RE49  -  [R_0402NEW]  194.54 27.57 180 top
RE50  -  [R_0402NEW]  50.97 105.23 180 bottom
RE60  -  [R_0402NEW]  228.31 156.4 90 bottom
RE70  -  [R_0402NEW]  192.94 54.63 270 top
RE71  -  [R_0402NEW]  178.51 42.57 0 top
RE326  -  [R_0402NEW]  179.49 48.91 180 top
RG1  -  [R_0402NEW]  74.96 45.74 270 top
RG2  -  [R_0402NEW]  68.66 45.62 270 top
RG3  -  [R_0402NEW]  146.87 103.22 270 bottom
RG4  -  [R_0402NEW]  70.95 44.7 90 top
RG5  -  [R_0402NEW]  72.93 39.01 270 top
RG6  -  [R_0402NEW]  119.24 136.55 90 top
RG7  -  [R_0402NEW]  174.17 98.21 90 bottom
RG8  -  [R_0402NEW]  35.2 75.64 90 bottom
RL19  -  [R_0603NEW]  20.29 85.55 270 top
RL20  -  [R_0603NEW]  20.29 81.74 90 top
RL27  -  [R_0402NEW]  42.88 79.39 0 bottom
RL31  -  [R_0402NEW]  35.08 79.37 90 bottom
RL33  -  [R_0402NEW]  42.97 85.55 180 bottom
RL34  -  [R_0402NEW]  42.97 83.77 180 bottom
RL35  -  [R_0402NEW]  42.97 84.66 180 bottom
RL37  -  [R_0402NEW]  37.05 88.2 90 bottom
RL38  -  [R_0402NEW]  41.43 79.75 90 bottom
RM11  -  [R_0402NEW]  115.09 147.7 90 top
RM13  -  [R_0402NEW]  115.98 148.61 270 top
RM25  -  [R0805_0OHM-NEW]  120.68 148.22 180 top
RM26  -  [R0805_0OHM-NEW]  96 148.47 180 top
RM110  -  [R_0402NEW]  104.17 148.68 270 top
RP36  -  [RP_0804_8P4R]  189.4 54.24 90 top
RP37  -  [RP_0804_8P4R]  138.97 115.16 0 bottom
RP39  -  [RP_0804_8P4R]  140.12 119.46 180 bottom
RP40  -  [RP_0804_8P4R]  138.46 112.04 0 bottom
RP41  -  [RP_0804_8P4R]  142.34 111.29 0 bottom
RP42  -  [RP_0804_8P4R]  148.18 112.74 180 top
RP43  -  [RP_0804_8P4R]  143.11 122.32 180 bottom
RP44  -  [RP_0804_8P4R]  86.46 123.7 180 bottom
RP45  -  [RP_0804_8P4R]  74.94 111.4 180 top
RP46  -  [RP_0804_8P4R]  60.6 89.48 90 bottom
RP47  -  [RP_0804_8P4R]  175.62 105.86 90 top
RP48  -  [RP_0804_8P4R]  86.89 110.99 0 bottom
RP49  -  [RP_0804_8P4R]  138.46 109.24 0 bottom
RP50  -  [RP_0804_8P4R]  132.18 111.34 180 top
RP51  -  [RP_0804_8P4R]  130.95 130.05 90 bottom
RP52  -  [RP_0804_8P4R]  20.02 109.73 90 bottom
RP53  -  [RP_0804_8P4R]  135.72 123.28 0 bottom
RP54  -  [RP_0804_8P4R]  132.18 114.13 180 top
RP55  -  [RP_0804_8P4R]  139.59 97.45 270 top
RP56  -  [RP_0804_8P4R]  200.06 175.47 180 top
RP57  -  [RP_0804_8P4R]  196.82 165.69 180 top
RP58  -  [RP_0804_8P4R]  15.21 96.48 180 top
RP59  -  [RP_0804_8P4R]  16.61 101.94 180 top
RP60  -  [RP_0804_8P4R]  184 105.92 90 top
RR1  -  [R_0402NEW]  175 18.07 270 top
RR2  -  [R_0402NEW]  178.21 27.11 90 top
RR3  -  [R_0402NEW]  180.88 20.94 0 top
RS6  -  [R_0402NEW]  222.67 126.3 0 bottom
RV1  -  [R_0402NEW]  218.6 143.09 270 bottom
RV2  -  [R_0402NEW]  218.52 140.41 0 bottom
RV3  -  [R_0402NEW]  218.46 126.44 0 bottom
RV4  -  [R_0402NEW]  218.46 124.66 0 bottom
RV5  -  [R_0402NEW]  201.41 133.68 180 bottom
RV6  -  [R_0402NEW]  200.5 131.9 0 bottom
RV7  -  [R_0402NEW]  218.71 124.66 0 top
RV8  -  [R_0402NEW]  219.62 126.44 180 top
RV9  -  [R_0402NEW]  206.4 142.62 90 top
RV10  -  [R_0402NEW]  204.63 143.53 270 top
RV11  -  [R_0402NEW]  201.46 131.86 180 top
RV12  -  [R_0402NEW]  200.55 129.68 0 top
RV13  -  [R_0402NEW]  212.64 102.06 180 bottom
RV14  -  [R_0402NEW]  211.73 100.28 0 bottom
RV15  -  [R_0402NEW]  206.15 101.81 270 bottom
RV16  -  [R_0402NEW]  204.37 100.9 90 bottom
RV17  -  [R_0402NEW]  201.22 111.88 180 top
RV19  -  [R_0402NEW]  200.31 113.66 0 top
RV20  -  [R_0402NEW]  214.53 100.1 270 top
RV21  -  [R_0402NEW]  212.75 99.18 90 top
RV22  -  [R_0402NEW]  218.46 120.09 0 top
RV23  -  [R_0402NEW]  218.46 118.31 0 top
RV24  -  [R_0402NEW]  201.22 111.88 180 bottom
RV25  -  [R_0402NEW]  172.11 138.19 90 top
RV26  -  [R_0402NEW]  172.11 138.19 90 bottom
RV27  -  [R_0402NEW]  200.31 113.66 0 bottom
RV28  -  [R_0402NEW]  158.13 150.32 0 top
RV29  -  [R_0402NEW]  169 139.1 270 bottom
RV30  -  [R_0402NEW]  191.35 138.12 90 bottom
RV31  -  [R_0402NEW]  191.35 138.12 90 top
RV32  -  [R_0402NEW]  200.96 157.05 180 top
RV33  -  [R_0402NEW]  200.04 155.27 0 top
RV34  -  [R_0402NEW]  159.05 152.09 180 top
RV35  -  [R_0402NEW]  177.07 157.3 270 bottom
RV36  -  [R_0402NEW]  178.84 156.39 90 bottom
RV37  -  [R_0402NEW]  169.89 138.19 90 bottom
RV38  -  [R_0402NEW]  177.07 157.3 270 top
RV39  -  [R_0402NEW]  187.35 139.04 270 bottom
RV40  -  [R_0402NEW]  200.5 155.98 270 bottom
RV41  -  [R_0402NEW]  202.34 155.06 90 bottom
RV42  -  [R_0402NEW]  172.62 126.87 90 top
RV43  -  [R_0402NEW]  173.51 126.87 90 top
RV44  -  [R_0402NEW]  186.16 127.26 180 top
RV45  -  [R_0402NEW]  186.16 128.15 180 top
RV46  -  [R_0402NEW]  186.39 126.25 0 top
RV47  -  [R_0402NEW]  190.85 126.83 270 top
RV48  -  [R_0402NEW]  187.47 115.77 0 top
RV49  -  [R_0402NEW]  190.16 115.77 180 top
RV54  -  [R0603_0OHM-NEW]  32.73 12.77 180 top
RV59  -  [R0603_0OHM-NEW]  19.65 25.79 270 top
RV64  -  [R_0402NEW]  178.32 105.99 0 top
RV66  -  [R_0402NEW]  161.72 112.54 180 bottom
RV67  -  [R_0402NEW]  194.34 99.56 90 bottom
RV68  -  [R_0402NEW]  194.34 102.25 270 bottom
RV69  -  [R_0402NEW]  191.8 99.56 90 bottom
RV70  -  [R_0402NEW]  191.8 102.25 270 bottom
RV71  -  [R_0402NEW]  192.88 99.56 90 bottom
RV73  -  [R_0402NEW]  190.86 102.24 180 bottom
RV74  -  [R_0402NEW]  189.97 98.37 180 bottom
RV75  -  [R_0402NEW]  181.7 96.64 90 bottom
RV76  -  [R_0402NEW]  182.59 96.64 90 bottom
RV81  -  [R_0402NEW]  183.48 96.64 90 bottom
RV82  -  [R_0402NEW]  184.37 96.64 90 bottom
RV83  -  [R_0402NEW]  185.26 96.64 90 bottom
RV84  -  [R_0402NEW]  158.51 112.53 0 bottom
RV85  -  [R_0402NEW]  187.29 105.92 90 top
RV89  -  [R_0402NEW]  181.64 104.41 270 top
RV90  -  [R_0402NEW]  179.92 93.4 90 top
RV91  -  [R_0402NEW]  175.16 92.54 270 top
RV93  -  [R_0402NEW]  185.01 100.46 180 bottom
RV95  -  [R_0402NEW]  185.01 101.35 180 bottom
RV96  -  [R_0402NEW]  175.36 96.35 270 bottom
RV97  -  [R_0402NEW]  171.43 102.05 180 bottom
RV98  -  [R_0402NEW]  175.36 93.68 90 bottom
RV103  -  [R_0805NEW]  168.3 127.86 270 top
RV105  -  [R_0402NEW]  175.54 158.49 90 bottom
RV107  -  [R_0402NEW]  189.26 92.13 90 bottom
RV108  -  [R_0402NEW]  189.26 93.91 90 bottom
RV109  -  [R_0402NEW]  173.31 92.59 0 bottom
RV118  -  [R0402_0OHM-NEW]  160.56 104.42 270 top
RV119  -  [R0402_0OHM-NEW]  182.54 99.13 180 bottom
RV120  -  [R0402_0OHM-NEW]  157.45 105.98 90 top
RV121  -  [R0402_0OHM-NEW]  186.86 99.2 180 bottom
RV122  -  [R_0402NEW]  183.22 102.25 270 bottom
RV123  -  [R_0402NEW]  173.11 104.27 0 top
RV124  -  [R0402_0OHM-NEW]  156.56 103.5 90 top
RV125  -  [R_0402NEW]  178.07 110.56 0 top
RV126  -  [R0402_0OHM-NEW]  157.57 100.33 90 top
RV127  -  [R_0402NEW]  161.84 107.83 180 bottom
RV133  -  [R_0402NEW]  169.69 115.83 0 top
RV136  -  [R_0402NEW]  193.43 93.35 0 top
RV137  -  [R_0402NEW]  192.44 91.51 180 top
RV138  -  [R_0402NEW]  210.91 99.05 90 top
RV139  -  [R_0402NEW]  162.03 130.63 180 bottom
RV140  -  [R_0402NEW]  162.02 131.57 180 bottom
RV141  -  [R_0402NEW]  196.14 101.49 90 bottom
RV142  -  [R_0402NEW]  197.96 105.04 90 bottom
RV143  -  [R_0402NEW]  209.96 99.97 270 top
RV144  -  [R_0402NEW]  207.61 99.37 90 top
RV145  -  [R_0402NEW]  206.66 99.37 90 top
RV146  -  [R_0402NEW]  161.11 129.74 0 bottom
RV147  -  [R_0402NEW]  161.11 132.46 0 bottom
RV148  -  [R_0402NEW]  197.09 103.27 90 bottom
RV149  -  [R_0402NEW]  197.07 105.95 270 bottom
RV162  -  [R_0402NEW]  200.55 127.39 0 top
RV163  -  [R_0402NEW]  200.5 129.68 0 bottom
RV169  -  [R_0402NEW]  200.31 110.55 0 top
RV171  -  [R_0402NEW]  200.31 110.55 0 bottom
RV181  -  [R_0402NEW]  178.84 156.39 90 top
RV183  -  [R_0402NEW]  169.89 138.19 90 top
RV184  -  [R_0402NEW]  168.11 139.1 270 top
RV185  -  [R_0402NEW]  158.13 149.43 0 top
RV186  -  [R_0402NEW]  159.05 147.65 180 top
RV191  -  [R_0402NEW]  181.51 156.27 90 top
RV192  -  [R_0402NEW]  179.73 156.27 90 top
RV193  -  [R_0402NEW]  189.13 138.12 90 top
RV194  -  [R_0402NEW]  187.35 139.04 270 top
RV195  -  [R_0402NEW]  182.4 157.06 270 bottom
RV196  -  [R_0402NEW]  180.62 156.14 90 bottom
RV197  -  [R_0402NEW]  189.13 138.12 90 bottom
RV198  -  [R_0402NEW]  171.22 119.44 90 top
RV199  -  [R_0402NEW]  182.54 94.36 180 top
RV201  -  [R_0402NEW]  154.99 110.19 270 top
RV202  -  [R_0402NEW]  173.4 115.72 180 top
RV203  -  [R_0402NEW]  164.49 98.99 270 top
RV204  -  [R_0402NEW]  172.82 112.34 180 top
RV206  -  [R_0402NEW]  176.25 125.78 180 top
RV207  -  [R_0402NEW]  166.22 112.08 180 top
RV215  -  [R_0402NEW]  179.11 107.45 180 top
RV234  -  [R_0603NEW]  165.26 126.5 180 top
RV235  -  [R_0402NEW]  175.92 101.27 90 bottom
RV236  -  [R_0402NEW]  174.91 102.19 270 bottom
RV237  -  [R_0402NEW]  166.38 98.99 270 top
RV238  -  [R_0402NEW]  168.24 98.07 90 top
RV239  -  [R_0402NEW]  158.4 109.27 90 top
RV240  -  [R_0402NEW]  159.28 110.19 270 top
RV241  -  [R_0402NEW]  160.81 112.54 270 top
RV242  -  [R_0402NEW]  158.52 111.62 90 top
RV243  -  [R_0402NEW]  156.87 109.27 90 top
RV244  -  [R_0402NEW]  154.33 115.14 270 top
RV245  -  [R_0402NEW]  153.38 115.14 270 top
RV246  -  [R_0402NEW]  171.36 110.75 180 top
RV247  -  [R_0402NEW]  167.02 108.4 0 top
RV248  -  [R0402_0OHM-NEW]  167.02 107.45 0 top
RV250  -  [R_0402NEW]  188.16 102.24 0 bottom
RV251  -  [R_0402NEW]  177.13 101.27 90 bottom
RV252  -  [R_0402NEW]  178.08 101.27 90 bottom
RX1  -  [R_0402NEW]  19.14 94.49 90 top
RX2  -  [R_0402NEW]  218.98 176.27 90 top
RX3  -  [R_0402NEW]  218.09 177.19 270 top
RX4  -  [R0805_0OHM-NEW]  202.05 165.89 180 bottom
RX5  -  [R_0402NEW]  198.71 166.72 0 top
RX6  -  [R_0402NEW]  199.33 163.14 90 bottom
RX7  -  [R_0402NEW]  216.88 166.84 270 top
RX8  -  [R_0402NEW]  215.99 166.84 270 top
RX9  -  [R_0402NEW]  219.82 167.02 180 bottom
RX12  -  [R_0402NEW]  15.09 110.55 180 bottom
RX13  -  [R_0402NEW]  22.95 108.35 270 bottom
RX14  -  [R_0402NEW]  19.19 115.26 0 bottom
RX15  -  [R_0402NEW]  15.09 112.34 180 bottom
RX16  -  [R_0402NEW]  14.02 108.27 90 top
RX17  -  [R_0402NEW]  14.02 107.4 270 top
RX18  -  [R_0402NEW]  211.36 175.88 0 top
RX19  -  [R0402_0OHM-NEW]  214.01 176.74 270 top
RX20  -  [R0402_0OHM-NEW]  212.27 176.77 180 top
RX21  -  [R_0402NEW]  218.98 165.73 90 top
RX22  -  [R_0402NEW]  219.87 165.73 90 top
RX23  -  [R_0402NEW]  213.12 176.74 270 top
RX24  -  [R_0402NEW]  20.03 94.49 90 top
RX25  -  [R_0402NEW]  197.63 171.1 180 top
RX26  -  [R_0402NEW]  203.99 165.25 270 bottom
RX27  -  [R0603_0OHM-NEW]  217.64 173.56 0 top
RX28  -  [R0603_0OHM-NEW]  26 94.44 90 bottom
RX30  -  [R_0402NEW]  196.71 172.35 0 top
RX31  -  [R_0402NEW]  198.45 163.14 90 bottom
RX33  -  [R_0402NEW]  204.68 177.37 0 top
RX34  -  [R_0402NEW]  14.19 113.22 90 bottom
RX35  -  [R_0402NEW]  198.61 172.67 180 bottom
RX36  -  [R_0402NEW]  206.53 165.25 270 bottom
RX37  -  [R_0402NEW]  201.02 172.25 0 bottom
RX38  -  [R_0402NEW]  206.53 172.04 0 bottom
RX39  -  [R_0402NEW]  201.02 171.36 0 bottom
RX40  -  [R_0402NEW]  206.53 171.16 0 bottom
RX41  -  [R_0402NEW]  201.02 170.47 0 bottom
RX42  -  [R_0402NEW]  206.53 170.27 0 bottom
RX43  -  [R_0402NEW]  201.02 169.58 0 bottom
RX44  -  [R_0402NEW]  206.53 169.38 0 bottom
RX45  -  [R_0402NEW]  201.02 168.69 0 bottom
RX46  -  [R_0402NEW]  206.53 168.49 0 bottom
RX47  -  [R_0402NEW]  201.02 167.8 0 bottom
RX48  -  [R_0402NEW]  206.53 167.6 0 bottom
RX49  -  [R_0402NEW]  205.64 165.25 270 bottom
RX50  -  [R_0402NEW]  213.57 162 0 bottom
RX51  -  [R_0402NEW]  207.42 164.34 90 bottom
RX52  -  [R_0402NEW]  198.61 171.78 180 bottom
RX53  -  [R_0402NEW]  208.74 176.99 0 top
RX168  -  [R_0402NEW]  197.64 176.81 270 bottom
RX169  -  [R_0402NEW]  197.64 174.11 90 bottom
RX170  -  [R_0402NEW]  198.53 175.89 90 bottom
RX171  -  [R_0402NEW]  198.53 175.03 270 bottom
SW1  -  [SW_SMT1-05-A_4P]  196.77 27.43 90 top
SW2  -  [SW_SMT1-05-A_4P]  202.92 39.99 180 bottom
T38  -  [TPC12]  116.56 113.31 0 top
T39  -  [TPC12]  89.99 117.2 180 bottom
T40  -  [TPC12]  91.57 117.29 0 top
T41  -  [TPC12]  94.78 118.1 0 top
T42  -  [TPC12]  88.58 117.71 180 bottom
T43  -  [TPC12]  93.47 117.24 0 top
T44  -  [TPC12]  92.41 112.57 0 top
T45  -  [TPC12]  94.26 112.47 0 top
T46  -  [TPC12]  95.63 112.98 0 top
T47  -  [TPC12]  90.01 110.56 180 bottom
T48  -  [TPC12]  93.94 114.11 0 top
T49  -  [TPC12]  93.57 111.04 0 top
T50  -  [TPC12]  94.91 116.78 0 top
T51  -  [TPC12]  94.26 115.45 0 top
T53  -  [TPC12]  122.01 120.66 0 top
T55  -  [TPC12]  122.3 109.29 0 top
T56  -  [TPC12]  124.77 114.54 0 top
T58  -  [TPC12]  122.63 112.48 0 top
T59  -  [TPC12]  125.57 113.45 0 top
T78  -  [TPC12]  182.52 111.87 270 top
T79  -  [TPC12]  174.96 110.17 270 top
T80  -  [TPC12]  169.67 116.79 270 top
T81  -  [TPC12]  171.16 116.83 270 top
T82  -  [TPC12]  162.22 134.29 90 bottom
T83  -  [TPC12]  193.37 102.51 90 bottom
T84  -  [TPC12]  166.03 101.83 90 bottom
T85  -  [TPC12]  161.47 113.56 180 bottom
T86  -  [TPC12]  163.56 114.2 180 bottom
T87  -  [TPC12]  163.1 112.46 180 bottom
T88  -  [TPC12]  161.92 114.88 180 bottom
T89  -  [TPC12]  163.7 116.17 180 bottom
T90  -  [TPC12]  172.55 108.94 0 top
T91  -  [TPC12]  173.03 110.3 0 top
T94  -  [TPC12]  40.69 78.59 180 bottom
T95  -  [TPC12]  40.17 81.11 180 bottom
T96  -  [TPC12]  40 79.82 180 bottom
T97  -  [TPC12]  133.76 112.72 180 bottom
T98  -  [TPC12]  135.33 112.8 180 bottom
T99  -  [TPC12]  133.02 111.34 180 bottom
T102  -  [TPC12]  126.95 111.57 0 top
T103  -  [TPC12]  136.3 98.31 0 top
T104  -  [TPC12]  128.02 110.63 0 top
T105  -  [TPC12]  128.09 109.3 0 top
T106  -  [TPC12]  133.57 106.39 180 bottom
T107  -  [TPC12]  123.72 111.07 0 top
T111  -  [TPC12]  88.85 122.52 0 top
T112  -  [TPC12]  88.61 121.74 180 bottom
T113  -  [TPC12]  94.29 120.59 0 top
T114  -  [TPC12]  90.52 122.31 0 top
T115  -  [TPC12]  93.89 119.16 0 top
T116  -  [TPC12]  92.59 120.36 0 top
T117  -  [TPC12]  127.8 112.55 0 top
T118  -  [TPC12]  123.23 99.85 0 top
T119  -  [TPC12]  124.12 105.74 0 top
T120  -  [TPC12]  122.02 123.55 0 top
T121  -  [TPC12]  123.5 125.52 0 top
T124  -  [TPC12]  128.98 117.52 0 top
T125  -  [TPC12]  133.45 114.45 180 bottom
T126  -  [TPC12]  129.63 109.45 0 top
T127  -  [TPC12]  128.36 107.9 0 top
T128  -  [TPC12]  135.19 104.82 180 bottom
T129  -  [TPC12]  116.4 119.3 0 top
T130  -  [TPC12]  115.59 117.82 0 top
T131  -  [TPC12]  115.88 116.25 0 top
T132  -  [TPC12]  102.65 99.91 180 bottom
T133  -  [TPC12]  124.26 117.08 0 top
T134  -  [TPC12]  103.76 101.2 180 bottom
T135  -  [TPC12]  121.85 125.4 0 top
T136  -  [TPC12]  133.63 108.15 180 bottom
T137  -  [TPC12]  124.35 107.12 0 top
T138  -  [TPC12]  118.08 122.82 0 top
T139  -  [TPC12]  134.75 98.26 0 top
T140  -  [TPC12]  117.44 121.61 0 top
T141  -  [TPC12]  124.97 98.11 0 top
T142  -  [TPC12]  123.5 101.52 0 top
T143  -  [TPC12]  118.65 119.33 0 top
T144  -  [TPC12]  124.46 99.1 180 bottom
T145  -  [TPC12]  123.6 100.65 180 bottom
T146  -  [TPC12]  89.13 97.09 180 bottom
T147  -  [TPC12]  87.58 96.36 180 bottom
T148  -  [TPC12]  88.62 125.25 180 bottom
T149  -  [TPC12]  88.53 123.97 180 bottom
T150  -  [TPC12]  104.55 128.92 180 bottom
T151  -  [TPC12]  98.86 127.41 180 bottom
T152  -  [TPC12]  99.98 128.73 180 bottom
T153  -  [TPC12]  88.61 119.01 180 bottom
T154  -  [TPC12]  92.06 118.67 0 top
T155  -  [TPC12]  115.58 114.73 0 top
T156  -  [TPC12]  117.41 114.89 0 top
T157  -  [TPC12]  88.79 98.96 180 bottom
T158  -  [TPC12]  93.18 128.89 180 bottom
T159  -  [TPC12]  130.03 128.55 180 bottom
T160  -  [TPC12]  120.29 117.61 0 top
T161  -  [TPC12]  133.29 124.05 180 bottom
T162  -  [TPC12]  120.03 116.12 0 top
T163  -  [TPC12]  134.41 124.69 180 bottom
T164  -  [TPC12]  117.64 120.22 0 top
T165  -  [TPC12]  120.14 121.05 0 top
T166  -  [TPC12]  90.33 99.36 180 bottom
T167  -  [TPC12]  133.57 126.66 180 bottom
T168  -  [TPC12]  133.5 128.03 180 bottom
T169  -  [TPC12]  89.4 129.86 180 bottom
T170  -  [TPC12]  88.58 127.44 180 bottom
T171  -  [TPC12]  133.7 104.66 180 bottom
T172  -  [TPC12]  134.09 102.35 180 bottom
T173  -  [TPC12]  90.68 97.6 180 bottom
T174  -  [TPC12]  126.86 113.55 0 top
T175  -  [TPC12]  126.94 118.35 0 top
T176  -  [TPC12]  126.28 119.55 0 top
T177  -  [TPC12]  127.66 117.24 0 top
T178  -  [TPC12]  125.25 118.36 0 top
T179  -  [TPC12]  132.08 120.33 180 bottom
T180  -  [TPC12]  132.43 121.58 180 bottom
T181  -  [TPC12]  134.41 122.05 180 bottom
T182  -  [TPC12]  126.18 109.54 0 top
T183  -  [TPC12]  151.36 81.11 180 bottom
T184  -  [TPC12]  153.18 81.11 180 bottom
T185  -  [TPC12]  153.11 78.7 180 bottom
T186  -  [TPC12]  151.34 78.66 180 bottom
TL1  -  [BOTH_NS0013LF_16P]  30.91 88.15 270 bottom
U2301  -  [TPS22966DPUR_SON14_2X3]  97.81 28.39 180 bottom
U2302  -  [W25Q64FVSSIG_SO8]  150.53 85.5 90 bottom
U2303  -  [74AUP1G07GW_TSSOP5]  43.47 66.04 0 top
U2304  -  [TPS22966DPUR_SON14_2X3]  140.75 22.1 0 top
UA1  -  [ALC3221-CG_MQFN48_6X6]  30.06 18.45 90 top
UC1  -  [HASWELL-MCP-E-ULT_BGA_1168P-T]  130.28 125.56 0 bottom
UC3  -  [MC74VHC1G08DFT2G_SC70-5]  148.25 105.93 180 top
UC4  -  [74CBTLV3126BQ_DHVQFN14_2P5X3]  71.1 106.53 270 bottom
UE1  -  [KB9012QF-A2_LQFP128_14X14]  183.19 35.68 0 top
UE2  -  [SN74LVC1G06DCKR_SC70-5]  178.13 52.42 0 top
UE3  -  [G993P1UF_SOP8]  46.26 103.37 0 bottom
UG1  -  [SLG3NB274VTR_TQFN16_2X3]  70.63 40.63 0 top
UI2  -  [AP2301MPG-13_MSOP8]  28.53 52.06 90 top
UI3  -  [AP2301MPG-13_MSOP8]  25.41 61.43 90 top
UI4  -  [AP2301MPG-13_MSOP8]  20.34 30.98 90 top
UI5  -  [AP2301MPG-13_MSOP8]  205.87 42.12 0 top
UL1  -  [RTL8106E-CG_QFN32_4X4]  35.67 82.87 90 bottom
UL2  -  [APL3512ABI-TRG_SOT23-5]  49.51 83.26 270 bottom
UR1  -  [RTS5179-GR_QFN24_4X4]  175.82 21.39 0 top
UV1  -  [2160809000A11SEYMOU_FCBGA_962P]  192.86 133.09 180 bottom
UV3  -  [K4G20325FC-HC05_FBGA_170P]  195.6 152.79 270 top
UV4  -  [K4G20325FC-HC05_FBGA_170P]  162.28 152.85 270 bottom
UV5  -  [K4G20325FC-HC05_FBGA_170P]  175.09 152.85 270 top
UV6  -  [K4G20325FC-HC05_FBGA_170P]  182.79 152.79 270 bottom
UV7  -  [K4G20325FC-HC05_FBGA_170P]  215.16 126.71 180 top
UV8  -  [K4G20325FC-HC05_FBGA_170P]  215.16 139.51 180 bottom
UV9  -  [K4G20325FC-HC05_FBGA_170P]  214.97 106.31 180 top
UV10  -  [K4G20325FC-HC05_FBGA_170P]  214.97 119.11 180 bottom
UV13  -  [MC74VHC1G08DFT2G_SC70-5]  158.91 109.09 90 bottom
UV14  -  [ADM1032ARMZ-2REEL_MSOP8]  178.55 94.25 180 bottom
UX1  -  [APL3512ABI-TRG_SOT23-5]  215.68 168.08 0 top
UX2  -  [MC74VHC1G08DFT2G_SC70-5]  210.43 161.22 90 bottom
UX4  -  [RTD2136R-CG_QFN48_6X6]  201.27 172.58 270 top
YC1  -  [Y_Q13FC1350000_2P]  146.86 100.72 0 bottom
YC2  -  [Y_X3G024000DC1H_4P]  115.52 135.76 0 top
YG1  -  [Y_FSX3M-25PM20FDO_4P]  63.7 39.53 0 top
YL2  -  [Y_FSX3M-25PM20FDO_4P]  36.77 78.15 0 bottom
YV1  -  [Y_7V27000011_4P]  172.39 98.21 180 bottom

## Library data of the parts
C35-C38 C50-C58 C61-C64 C67-C69 C71 C73 C75-C77 C81 C83 C85 C87 C88 C2326 C2327 C5212 CA21 CA22 CA24 CA25 CA29-CA33 CA38-CA40 CA51 CA54 CA56 CA58 CA60 CA65 CA69 CC14 CC15 CC23 CC25 CC32 CC40 CD31 CE5 CE6 CE11 CE12 CE15 CE18-CE20 CE23 CE24 CE26-CE33 CG1-CG4 CG7-CG11 CI2-CI4 CI7 CI9-CI11 CI13-CI17 CI19 CI22 CI24-CI26 CI30 CI32 CL15 CL19 CL20 CL22 CL26 CL30 CL31 CL34-CL37 CL39 CL41 CM40 CM44 CM46-CM49 CR1 CR3-CR7 CR9-CR11 CS5 CS6 CS8-CS11 CS13-CS15 CS17 CS105 CS106 CS108 CS109 CV8-CV40 CV43-CV50 CV59-CV76 CV78 CV79 CV81 CV83-CV85 CV87-CV89 CV92-CV95 CV108 CV109 CV112-CV115 CV118 CV119 CV121 CV122 CV124-CV130 CV132 CV133 CV141-CV150 CV152-CV156 CV171-CV174 CV188-CV190 CV193-CV196 CV198 CV199 CV201-CV212 CV216-CV224 CV280 CV281 CV283-CV288 CV290-CV299 CV301-CV308 CV310-CV313 CV315 CV316 CV318 CV319 CV325 CV326 CV328-CV333 CV335 CV349-CV356 CV368-CV401 CX1 CX2 CX4 CX6 CX9-CX21 CX23-CX34 CX37-CX44 CX46 CX47 PC1-PC5 PC7 PC8 PC13-PC16 PC102 PC104 PC108 PC110 PC113 PC114 PC201-PC203 PC207 PC208 PC210 PC300 PC303 PC304 PC307 PC401 PC403 PC404 PC501 PC502 PC504 PC506 PC507 PC509-PC514 PC519-PC522 PC601 PC603 PC604 PC702 PC705 PC708 PC711 PC715 PC717 PC719 PC720 PC722 PC723 PC806 PC809 PC813 PC814 PC816-PC821 PC831 PC832 PC840-PC866 PC869 PC871-PC873 PC1100 PC1101 PC1104 PC1106 PC1200 PC1203 PC1209 PC1214 PC1302 PC1304 PC1306 PC1307 = C_0402NEW
C39 C41 C42 C45 C60 C66 C72 C74 C78 C82 C2305 C2306 C2308 C2309 C2311-C2314 C2316 C2318 C2322-C2324 CA1 CA2 CA23 CA53 CA55 CA57 CA59 CA61-CA64 CA67 CA68 CA71 CA74 CC26 CD59 CE22 CE25 CG6 CI40 CI43 CI44 CL38 CM43 CR2 CR8 CS16 CV1 CV3-CV7 CV41 CV42 CV77 CV80 CV82 CV86 CV91 CV101-CV103 CV110 CV111 CV116 CV117 CV120 CV123 CV131 CV134 CV136-CV140 CV151 CV170 CV187 CV197 CV200 CV213-CV215 CV322-CV324 CX5 CX22 CX35 CX45 PC100 PC103 PC105 PC106 PC109 PC111 PC200 PC204 PC209 PC301 PC302 PC312 PC313 PC503 PC505 PC508 PC701 PC706 PC707 PC709 PC710 PC721 PC803 PC807 PC810 PC811 PC815 PC835 PC867 PC868 PC870 PC1103 PC1105 PC1205 PC1210 PC1212 PC1213 = C_0603NEW
C59 C65 C70 C84 C86 CL33 = C_1206NEW
